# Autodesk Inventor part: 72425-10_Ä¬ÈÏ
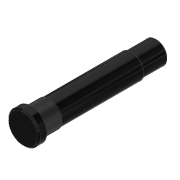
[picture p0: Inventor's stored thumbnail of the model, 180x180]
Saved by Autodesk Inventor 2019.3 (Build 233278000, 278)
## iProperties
Created: 2010-06
Part Number: 72425-10_Ä¬ÈÏ
Material: Ogólny
Document SubType Name: Modeling
Designer: CADENGINEERING4
Density: 1 g/cm^3
Appearance: Gładki — czarny
Author: CADENGINEERING4
Revision Number: ÈÎºÎ
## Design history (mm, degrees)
feature "NONE"
node "Bryła1"
